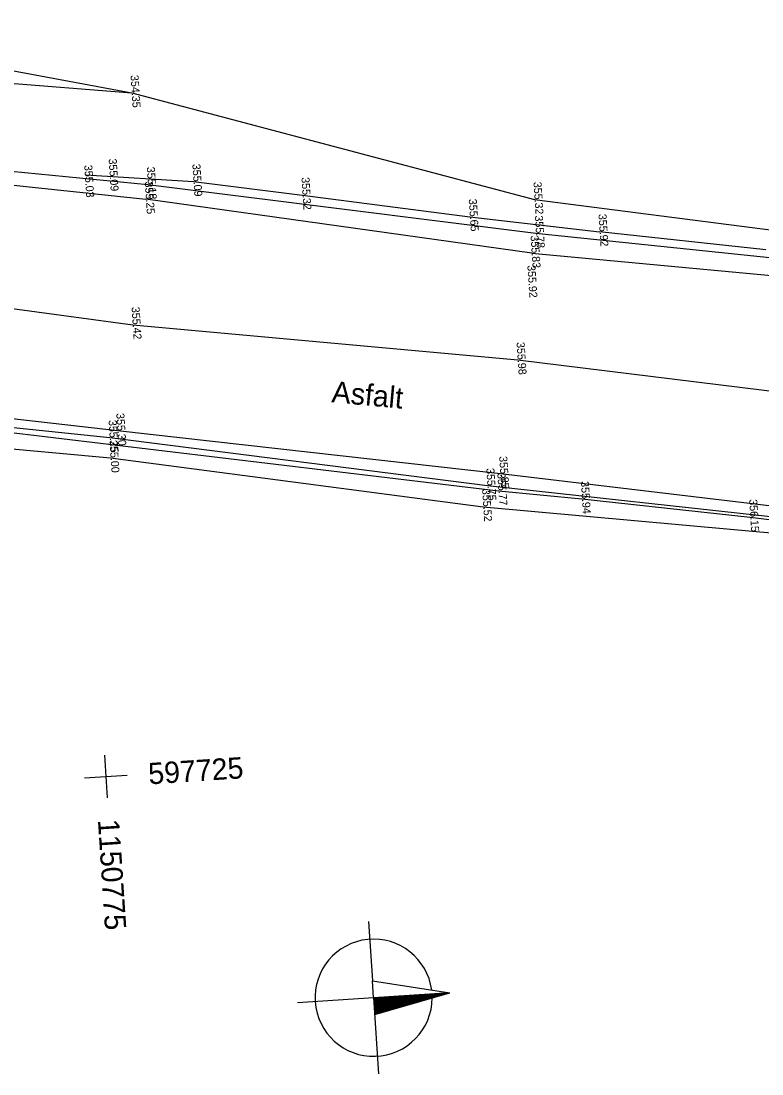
# Model space of a CAD drawing. Extents: x -600096 to -597522, y -1151695 to -1149849.
# Drawn here: x -599571.03 to -599553.67, y -1151449.97 to -1151425.31 of the extents above; entities that cross this region are included whole.
import ezdxf

# ---------------------------------------------------------------- set-up
doc = ezdxf.new("R2010")
doc.units = 0
for name, color, linetype in [('Hrana komunikace', 7, 'Continuous'), ('MPPV_Dno_prikopu', 7, 'Continuous'), ('MPPV_komunikace', 7, 'Continuous'), ('MPPV_svah', 7, 'Continuous'), ('MPPV_vodorovne_znaceni', 7, 'Continuous'), ('Popis', 7, 'Continuous'), ('rám', 7, 'Continuous'), ('Svodidla', 7, 'Continuous'), ('Tabulka', 7, 'Continuous'), ('Vrstva 12', 7, 'Continuous'), ('Vrstva 5', 7, 'Continuous')]:
    doc.layers.add(name, color=color, linetype=linetype)

msp = doc.modelspace()

# ---------------------------------------------------------------- linework, layer by layer
at = {"layer": 'Hrana komunikace'}
for p, q in [((-599577.687, -1151428.205), (-599568.056, -1151429.139)), ((-599568.056, -1151429.139), (-599558.962, -1151430.28)), ((-599558.962, -1151430.28), (-599551.698, -1151431.028)), ((-599568.951, -1151435.07), (-599578.396, -1151434.083)), ((-599560.099, -1151436.196), (-599568.951, -1151435.07)), ((-599552.65, -1151437.013), (-599560.099, -1151436.196))]:
    msp.add_line(p, q, dxfattribs=at)
at = {"layer": 'MPPV_Dno_prikopu'}
msp.add_line((-599577.724, -1151426.253), (-599568.437, -1151426.99), dxfattribs=at)
at = {"layer": 'MPPV_komunikace'}
for p, q in [((-599577.67, -1151428.464), (-599568.103, -1151429.483)), ((-599559.062, -1151430.747), (-599568.103, -1151429.483)), ((-599559.062, -1151430.747), (-599551.661, -1151431.436)), ((-599568.772, -1151434.908), (-599578.354, -1151433.8)), ((-599559.797, -1151435.916), (-599568.772, -1151434.908)), ((-599552.616, -1151436.77), (-599559.797, -1151435.916))]:
    msp.add_line(p, q, dxfattribs=at)
at = {"layer": 'MPPV_svah'}
for p, q in [((-599577.525, -1151425.308), (-599568.437, -1151426.99)), ((-599568.437, -1151426.99), (-599558.994, -1151429.49)), ((-599558.994, -1151429.49), (-599551.627, -1151430.432)), ((-599578.539, -1151434.654), (-599568.931, -1151435.54)), ((-599568.931, -1151435.54), (-599560.198, -1151436.684)), ((-599560.198, -1151436.684), (-599552.758, -1151437.36))]:
    msp.add_line(p, q, dxfattribs=at)
at = {"layer": 'MPPV_vodorovne_znaceni'}
for p, q in [((-599578.149, -1151431.111), (-599568.413, -1151432.42)), ((-599568.413, -1151432.42), (-599559.39, -1151433.244)), ((-599559.39, -1151433.244), (-599552.227, -1151434.129))]:
    msp.add_line(p, q, dxfattribs=at)
at = {"layer": 'rám'}
for p, q in [((-599562.767, -1151448.185), (-599562.767, -1151448.197)), ((-599562.762, -1151448.184), (-599562.764, -1151448.24)), ((-599562.757, -1151448.184), (-599562.761, -1151448.284)), ((-599562.752, -1151448.184), (-599562.758, -1151448.327)), ((-599562.747, -1151448.183), (-599562.755, -1151448.371)), ((-599562.742, -1151448.183), (-599562.753, -1151448.415)), ((-599562.737, -1151448.183), (-599562.75, -1151448.458)), ((-599562.732, -1151448.183), (-599562.747, -1151448.502)), ((-599562.727, -1151448.182), (-599562.744, -1151448.546)), ((-599562.721, -1151448.182), (-599562.74, -1151448.58)), ((-599562.716, -1151448.182), (-599562.735, -1151448.579)), ((-599562.711, -1151448.181), (-599562.73, -1151448.577)), ((-599562.706, -1151448.181), (-599562.725, -1151448.576)), ((-599562.701, -1151448.181), (-599562.72, -1151448.574)), ((-599562.696, -1151448.18), (-599562.715, -1151448.573)), ((-599562.691, -1151448.18), (-599562.71, -1151448.571)), ((-599562.686, -1151448.18), (-599562.705, -1151448.57)), ((-599562.681, -1151448.179), (-599562.7, -1151448.568)), ((-599562.676, -1151448.179), (-599562.695, -1151448.567)), ((-599562.671, -1151448.179), (-599562.69, -1151448.565)), ((-599562.666, -1151448.178), (-599562.685, -1151448.564)), ((-599562.661, -1151448.178), (-599562.679, -1151448.562)), ((-599562.656, -1151448.178), (-599562.674, -1151448.561)), ((-599562.651, -1151448.177), (-599562.669, -1151448.56)), ((-599562.646, -1151448.177), (-599562.664, -1151448.558)), ((-599562.641, -1151448.177), (-599562.659, -1151448.557)), ((-599562.636, -1151448.176), (-599562.654, -1151448.555)), ((-599562.631, -1151448.176), (-599562.649, -1151448.554)), ((-599562.626, -1151448.176), (-599562.644, -1151448.552)), ((-599562.621, -1151448.175), (-599562.639, -1151448.551)), ((-599562.616, -1151448.175), (-599562.634, -1151448.549)), ((-599562.611, -1151448.175), (-599562.629, -1151448.548)), ((-599562.606, -1151448.174), (-599562.624, -1151448.546)), ((-599562.601, -1151448.174), (-599562.619, -1151448.545)), ((-599562.596, -1151448.174), (-599562.613, -1151448.543)), ((-599562.591, -1151448.173), (-599562.608, -1151448.542)), ((-599562.586, -1151448.173), (-599562.603, -1151448.54)), ((-599562.581, -1151448.173), (-599562.598, -1151448.539)), ((-599562.576, -1151448.172), (-599562.593, -1151448.537)), ((-599562.571, -1151448.172), (-599562.588, -1151448.536)), ((-599562.566, -1151448.172), (-599562.583, -1151448.534)), ((-599562.561, -1151448.171), (-599562.578, -1151448.533)), ((-599562.556, -1151448.171), (-599562.573, -1151448.531)), ((-599562.551, -1151448.171), (-599562.568, -1151448.53)), ((-599562.546, -1151448.17), (-599562.563, -1151448.528)), ((-599562.541, -1151448.17), (-599562.558, -1151448.527)), ((-599562.536, -1151448.17), (-599562.553, -1151448.526)), ((-599562.531, -1151448.169), (-599562.547, -1151448.524)), ((-599562.526, -1151448.169), (-599562.542, -1151448.523)), ((-599562.521, -1151448.169), (-599562.537, -1151448.521)), ((-599562.516, -1151448.168), (-599562.532, -1151448.52)), ((-599562.511, -1151448.168), (-599562.527, -1151448.518)), ((-599562.506, -1151448.168), (-599562.522, -1151448.517)), ((-599562.501, -1151448.167), (-599562.517, -1151448.515)), ((-599562.496, -1151448.167), (-599562.512, -1151448.514)), ((-599562.491, -1151448.167), (-599562.507, -1151448.512)), ((-599562.486, -1151448.166), (-599562.502, -1151448.511)), ((-599562.48, -1151448.166), (-599562.497, -1151448.509)), ((-599562.475, -1151448.166), (-599562.492, -1151448.508)), ((-599562.47, -1151448.165), (-599562.487, -1151448.506)), ((-599562.465, -1151448.165), (-599562.481, -1151448.505)), ((-599562.46, -1151448.165), (-599562.476, -1151448.503)), ((-599562.455, -1151448.164), (-599562.471, -1151448.502)), ((-599562.45, -1151448.164), (-599562.466, -1151448.5)), ((-599562.445, -1151448.164), (-599562.461, -1151448.499)), ((-599562.44, -1151448.164), (-599562.456, -1151448.497)), ((-599562.435, -1151448.163), (-599562.451, -1151448.496)), ((-599562.43, -1151448.163), (-599562.446, -1151448.494)), ((-599562.425, -1151448.163), (-599562.441, -1151448.493)), ((-599562.42, -1151448.162), (-599562.436, -1151448.492)), ((-599562.415, -1151448.162), (-599562.431, -1151448.49)), ((-599562.41, -1151448.162), (-599562.426, -1151448.489)), ((-599562.405, -1151448.161), (-599562.421, -1151448.487)), ((-599562.4, -1151448.161), (-599562.416, -1151448.486)), ((-599562.395, -1151448.161), (-599562.41, -1151448.484)), ((-599562.39, -1151448.16), (-599562.405, -1151448.483)), ((-599562.385, -1151448.16), (-599562.4, -1151448.481)), ((-599562.38, -1151448.16), (-599562.395, -1151448.48)), ((-599562.375, -1151448.159), (-599562.39, -1151448.478)), ((-599562.37, -1151448.159), (-599562.385, -1151448.477)), ((-599562.365, -1151448.159), (-599562.38, -1151448.475)), ((-599562.36, -1151448.158), (-599562.375, -1151448.474)), ((-599562.355, -1151448.158), (-599562.37, -1151448.472)), ((-599562.35, -1151448.158), (-599562.365, -1151448.471)), ((-599562.345, -1151448.157), (-599562.36, -1151448.469)), ((-599562.34, -1151448.157), (-599562.355, -1151448.468)), ((-599562.335, -1151448.157), (-599562.35, -1151448.466)), ((-599562.33, -1151448.156), (-599562.344, -1151448.465)), ((-599562.325, -1151448.156), (-599562.339, -1151448.463)), ((-599562.32, -1151448.156), (-599562.334, -1151448.462)), ((-599562.315, -1151448.155), (-599562.329, -1151448.461)), ((-599562.31, -1151448.155), (-599562.324, -1151448.459)), ((-599562.305, -1151448.155), (-599562.319, -1151448.458)), ((-599562.3, -1151448.154), (-599562.314, -1151448.456)), ((-599562.295, -1151448.154), (-599562.309, -1151448.455)), ((-599562.29, -1151448.154), (-599562.304, -1151448.453)), ((-599562.285, -1151448.153), (-599562.299, -1151448.452)), ((-599562.28, -1151448.153), (-599562.294, -1151448.45)), ((-599562.275, -1151448.153), (-599562.289, -1151448.449)), ((-599562.27, -1151448.152), (-599562.284, -1151448.447)), ((-599562.265, -1151448.152), (-599562.278, -1151448.446)), ((-599562.26, -1151448.152), (-599562.273, -1151448.444)), ((-599562.255, -1151448.151), (-599562.268, -1151448.443)), ((-599562.25, -1151448.151), (-599562.263, -1151448.441)), ((-599562.244, -1151448.151), (-599562.258, -1151448.44)), ((-599562.239, -1151448.15), (-599562.253, -1151448.438)), ((-599562.234, -1151448.15), (-599562.248, -1151448.437)), ((-599562.229, -1151448.15), (-599562.243, -1151448.435)), ((-599562.224, -1151448.149), (-599562.238, -1151448.434)), ((-599562.219, -1151448.149), (-599562.233, -1151448.432)), ((-599562.214, -1151448.149), (-599562.228, -1151448.431)), ((-599562.209, -1151448.148), (-599562.223, -1151448.429)), ((-599562.204, -1151448.148), (-599562.218, -1151448.428)), ((-599562.199, -1151448.148), (-599562.212, -1151448.427)), ((-599562.194, -1151448.147), (-599562.207, -1151448.425)), ((-599562.189, -1151448.147), (-599562.202, -1151448.424)), ((-599562.184, -1151448.147), (-599562.197, -1151448.422)), ((-599562.179, -1151448.146), (-599562.192, -1151448.421)), ((-599562.174, -1151448.146), (-599562.187, -1151448.419)), ((-599562.169, -1151448.146), (-599562.182, -1151448.418)), ((-599562.164, -1151448.145), (-599562.177, -1151448.416)), ((-599562.159, -1151448.145), (-599562.172, -1151448.415)), ((-599562.154, -1151448.145), (-599562.167, -1151448.413)), ((-599562.149, -1151448.144), (-599562.162, -1151448.412)), ((-599562.144, -1151448.144), (-599562.157, -1151448.41)), ((-599562.139, -1151448.144), (-599562.152, -1151448.409)), ((-599562.134, -1151448.144), (-599562.147, -1151448.407)), ((-599562.129, -1151448.143), (-599562.141, -1151448.406)), ((-599562.124, -1151448.143), (-599562.136, -1151448.404)), ((-599562.119, -1151448.143), (-599562.131, -1151448.403)), ((-599562.114, -1151448.142), (-599562.126, -1151448.401)), ((-599562.109, -1151448.142), (-599562.121, -1151448.4)), ((-599562.104, -1151448.142), (-599562.116, -1151448.398)), ((-599562.099, -1151448.141), (-599562.111, -1151448.397)), ((-599562.094, -1151448.141), (-599562.106, -1151448.395)), ((-599562.089, -1151448.141), (-599562.101, -1151448.394)), ((-599562.084, -1151448.14), (-599562.096, -1151448.393)), ((-599562.079, -1151448.14), (-599562.091, -1151448.391)), ((-599562.074, -1151448.14), (-599562.086, -1151448.39)), ((-599562.069, -1151448.139), (-599562.081, -1151448.388)), ((-599562.064, -1151448.139), (-599562.075, -1151448.387)), ((-599562.059, -1151448.139), (-599562.07, -1151448.385)), ((-599562.054, -1151448.138), (-599562.065, -1151448.384)), ((-599562.049, -1151448.138), (-599562.06, -1151448.382)), ((-599562.044, -1151448.138), (-599562.055, -1151448.381)), ((-599562.039, -1151448.137), (-599562.05, -1151448.379)), ((-599562.034, -1151448.137), (-599562.045, -1151448.378)), ((-599562.029, -1151448.137), (-599562.04, -1151448.376)), ((-599562.024, -1151448.136), (-599562.035, -1151448.375)), ((-599562.019, -1151448.136), (-599562.03, -1151448.373)), ((-599562.014, -1151448.136), (-599562.025, -1151448.372)), ((-599562.008, -1151448.135), (-599562.02, -1151448.37)), ((-599562.003, -1151448.135), (-599562.015, -1151448.369)), ((-599561.998, -1151448.135), (-599562.009, -1151448.367)), ((-599561.993, -1151448.134), (-599562.004, -1151448.366)), ((-599561.988, -1151448.134), (-599561.999, -1151448.364)), ((-599561.983, -1151448.134), (-599561.994, -1151448.363)), ((-599561.978, -1151448.133), (-599561.989, -1151448.361)), ((-599561.973, -1151448.133), (-599561.984, -1151448.36)), ((-599561.968, -1151448.133), (-599561.979, -1151448.359)), ((-599561.963, -1151448.132), (-599561.974, -1151448.357)), ((-599561.958, -1151448.132), (-599561.969, -1151448.356)), ((-599561.953, -1151448.132), (-599561.964, -1151448.354)), ((-599561.948, -1151448.131), (-599561.959, -1151448.353)), ((-599561.943, -1151448.131), (-599561.954, -1151448.351)), ((-599561.938, -1151448.131), (-599561.949, -1151448.35)), ((-599561.933, -1151448.13), (-599561.943, -1151448.348)), ((-599561.928, -1151448.13), (-599561.938, -1151448.347)), ((-599561.923, -1151448.13), (-599561.933, -1151448.345)), ((-599561.918, -1151448.129), (-599561.928, -1151448.344)), ((-599561.913, -1151448.129), (-599561.923, -1151448.342)), ((-599561.908, -1151448.129), (-599561.918, -1151448.341)), ((-599561.903, -1151448.128), (-599561.913, -1151448.339)), ((-599561.898, -1151448.128), (-599561.908, -1151448.338)), ((-599561.893, -1151448.128), (-599561.903, -1151448.336)), ((-599561.888, -1151448.127), (-599561.898, -1151448.335)), ((-599561.883, -1151448.127), (-599561.893, -1151448.333)), ((-599561.878, -1151448.127), (-599561.888, -1151448.332)), ((-599561.873, -1151448.126), (-599561.883, -1151448.33)), ((-599561.868, -1151448.126), (-599561.878, -1151448.329)), ((-599561.863, -1151448.126), (-599561.872, -1151448.327)), ((-599561.858, -1151448.125), (-599561.867, -1151448.326)), ((-599561.853, -1151448.125), (-599561.862, -1151448.325)), ((-599561.848, -1151448.125), (-599561.857, -1151448.323)), ((-599561.843, -1151448.125), (-599561.852, -1151448.322)), ((-599561.838, -1151448.124), (-599561.847, -1151448.32)), ((-599561.833, -1151448.124), (-599561.842, -1151448.319)), ((-599561.828, -1151448.124), (-599561.837, -1151448.317)), ((-599561.823, -1151448.123), (-599561.832, -1151448.316)), ((-599561.818, -1151448.123), (-599561.827, -1151448.314)), ((-599561.813, -1151448.123), (-599561.822, -1151448.313)), ((-599561.808, -1151448.122), (-599561.817, -1151448.311)), ((-599561.803, -1151448.122), (-599561.812, -1151448.31)), ((-599561.798, -1151448.122), (-599561.806, -1151448.308)), ((-599561.793, -1151448.121), (-599561.801, -1151448.307)), ((-599561.788, -1151448.121), (-599561.796, -1151448.305)), ((-599561.783, -1151448.121), (-599561.791, -1151448.304)), ((-599561.778, -1151448.12), (-599561.786, -1151448.302)), ((-599561.773, -1151448.12), (-599561.781, -1151448.301)), ((-599561.767, -1151448.12), (-599561.776, -1151448.299)), ((-599561.762, -1151448.119), (-599561.771, -1151448.298)), ((-599561.757, -1151448.119), (-599561.766, -1151448.296)), ((-599561.752, -1151448.119), (-599561.761, -1151448.295)), ((-599561.747, -1151448.118), (-599561.756, -1151448.294)), ((-599561.742, -1151448.118), (-599561.751, -1151448.292)), ((-599561.737, -1151448.118), (-599561.746, -1151448.291)), ((-599561.732, -1151448.117), (-599561.74, -1151448.289)), ((-599561.727, -1151448.117), (-599561.735, -1151448.288)), ((-599561.722, -1151448.117), (-599561.73, -1151448.286)), ((-599561.717, -1151448.116), (-599561.725, -1151448.285)), ((-599561.712, -1151448.116), (-599561.72, -1151448.283)), ((-599561.707, -1151448.116), (-599561.715, -1151448.282)), ((-599561.702, -1151448.115), (-599561.71, -1151448.28)), ((-599561.697, -1151448.115), (-599561.705, -1151448.279)), ((-599561.692, -1151448.115), (-599561.7, -1151448.277)), ((-599561.687, -1151448.114), (-599561.695, -1151448.276)), ((-599561.682, -1151448.114), (-599561.69, -1151448.274)), ((-599561.677, -1151448.114), (-599561.685, -1151448.273)), ((-599561.672, -1151448.113), (-599561.68, -1151448.271)), ((-599561.667, -1151448.113), (-599561.674, -1151448.27)), ((-599561.662, -1151448.113), (-599561.669, -1151448.268)), ((-599561.657, -1151448.112), (-599561.664, -1151448.267)), ((-599561.652, -1151448.112), (-599561.659, -1151448.265)), ((-599561.647, -1151448.112), (-599561.654, -1151448.264)), ((-599561.642, -1151448.111), (-599561.649, -1151448.262)), ((-599561.637, -1151448.111), (-599561.644, -1151448.261)), ((-599561.632, -1151448.111), (-599561.639, -1151448.26)), ((-599561.627, -1151448.11), (-599561.634, -1151448.258)), ((-599561.622, -1151448.11), (-599561.629, -1151448.257)), ((-599561.617, -1151448.11), (-599561.624, -1151448.255)), ((-599561.612, -1151448.109), (-599561.619, -1151448.254)), ((-599561.607, -1151448.109), (-599561.614, -1151448.252)), ((-599561.602, -1151448.109), (-599561.609, -1151448.251)), ((-599561.597, -1151448.108), (-599561.603, -1151448.249)), ((-599561.592, -1151448.108), (-599561.598, -1151448.248)), ((-599561.587, -1151448.108), (-599561.593, -1151448.246)), ((-599561.582, -1151448.107), (-599561.588, -1151448.245)), ((-599561.577, -1151448.107), (-599561.583, -1151448.243)), ((-599561.572, -1151448.107), (-599561.578, -1151448.242)), ((-599561.567, -1151448.106), (-599561.573, -1151448.24)), ((-599561.562, -1151448.106), (-599561.568, -1151448.239)), ((-599561.557, -1151448.106), (-599561.563, -1151448.237)), ((-599561.552, -1151448.105), (-599561.558, -1151448.236)), ((-599561.547, -1151448.105), (-599561.553, -1151448.234)), ((-599561.542, -1151448.105), (-599561.548, -1151448.233)), ((-599561.537, -1151448.105), (-599561.543, -1151448.231)), ((-599561.531, -1151448.104), (-599561.537, -1151448.23)), ((-599561.526, -1151448.104), (-599561.532, -1151448.228)), ((-599561.521, -1151448.104), (-599561.527, -1151448.227)), ((-599561.516, -1151448.103), (-599561.522, -1151448.226)), ((-599561.511, -1151448.103), (-599561.517, -1151448.224)), ((-599561.506, -1151448.103), (-599561.512, -1151448.223)), ((-599561.501, -1151448.102), (-599561.507, -1151448.221)), ((-599561.496, -1151448.102), (-599561.502, -1151448.22)), ((-599561.491, -1151448.102), (-599561.497, -1151448.218)), ((-599561.486, -1151448.101), (-599561.492, -1151448.217)), ((-599561.481, -1151448.101), (-599561.487, -1151448.215)), ((-599561.476, -1151448.101), (-599561.482, -1151448.214)), ((-599561.471, -1151448.1), (-599561.477, -1151448.212)), ((-599561.466, -1151448.1), (-599561.471, -1151448.211)), ((-599561.461, -1151448.1), (-599561.466, -1151448.209)), ((-599561.456, -1151448.099), (-599561.461, -1151448.208)), ((-599561.451, -1151448.099), (-599561.456, -1151448.206)), ((-599561.446, -1151448.099), (-599561.451, -1151448.205)), ((-599561.441, -1151448.098), (-599561.446, -1151448.203)), ((-599561.436, -1151448.098), (-599561.441, -1151448.202)), ((-599561.431, -1151448.098), (-599561.436, -1151448.2)), ((-599561.426, -1151448.097), (-599561.431, -1151448.199)), ((-599561.421, -1151448.097), (-599561.426, -1151448.197)), ((-599561.416, -1151448.097), (-599561.421, -1151448.196)), ((-599561.411, -1151448.096), (-599561.416, -1151448.194)), ((-599561.406, -1151448.096), (-599561.411, -1151448.193)), ((-599561.401, -1151448.096), (-599561.405, -1151448.192)), ((-599561.396, -1151448.095), (-599561.4, -1151448.19)), ((-599561.391, -1151448.095), (-599561.395, -1151448.189)), ((-599561.386, -1151448.095), (-599561.39, -1151448.187)), ((-599561.381, -1151448.094), (-599561.385, -1151448.186)), ((-599561.376, -1151448.094), (-599561.38, -1151448.184)), ((-599561.371, -1151448.094), (-599561.375, -1151448.183)), ((-599561.366, -1151448.093), (-599561.37, -1151448.181)), ((-599561.361, -1151448.093), (-599561.365, -1151448.18)), ((-599561.356, -1151448.093), (-599561.36, -1151448.178)), ((-599561.351, -1151448.092), (-599561.355, -1151448.177)), ((-599561.346, -1151448.092), (-599561.35, -1151448.175)), ((-599561.341, -1151448.092), (-599561.345, -1151448.174)), ((-599561.336, -1151448.091), (-599561.339, -1151448.172)), ((-599561.331, -1151448.091), (-599561.334, -1151448.171)), ((-599561.326, -1151448.091), (-599561.329, -1151448.169)), ((-599561.321, -1151448.09), (-599561.324, -1151448.168)), ((-599561.316, -1151448.09), (-599561.319, -1151448.166)), ((-599561.311, -1151448.09), (-599561.314, -1151448.165)), ((-599561.306, -1151448.089), (-599561.309, -1151448.163)), ((-599561.301, -1151448.089), (-599561.304, -1151448.162)), ((-599561.295, -1151448.089), (-599561.299, -1151448.161)), ((-599561.29, -1151448.088), (-599561.294, -1151448.159)), ((-599561.285, -1151448.088), (-599561.289, -1151448.158)), ((-599561.28, -1151448.088), (-599561.284, -1151448.156)), ((-599561.275, -1151448.087), (-599561.279, -1151448.155)), ((-599561.27, -1151448.087), (-599561.274, -1151448.153)), ((-599561.265, -1151448.087), (-599561.268, -1151448.152)), ((-599561.26, -1151448.086), (-599561.263, -1151448.15)), ((-599561.255, -1151448.086), (-599561.258, -1151448.149)), ((-599561.25, -1151448.086), (-599561.253, -1151448.147)), ((-599561.245, -1151448.085), (-599561.248, -1151448.146)), ((-599561.24, -1151448.085), (-599561.243, -1151448.144)), ((-599561.235, -1151448.085), (-599561.238, -1151448.143)), ((-599561.23, -1151448.085), (-599561.233, -1151448.141)), ((-599561.225, -1151448.084), (-599561.228, -1151448.14)), ((-599561.22, -1151448.084), (-599561.223, -1151448.138)), ((-599561.215, -1151448.084), (-599561.218, -1151448.137)), ((-599561.21, -1151448.083), (-599561.213, -1151448.135)), ((-599561.205, -1151448.083), (-599561.208, -1151448.134)), ((-599561.2, -1151448.083), (-599561.202, -1151448.132)), ((-599561.195, -1151448.082), (-599561.197, -1151448.131)), ((-599561.19, -1151448.082), (-599561.192, -1151448.129)), ((-599561.185, -1151448.082), (-599561.187, -1151448.128)), ((-599561.18, -1151448.081), (-599561.182, -1151448.127)), ((-599561.175, -1151448.081), (-599561.177, -1151448.125)), ((-599561.17, -1151448.081), (-599561.172, -1151448.124)), ((-599561.165, -1151448.08), (-599561.167, -1151448.122)), ((-599561.16, -1151448.08), (-599561.162, -1151448.121)), ((-599561.155, -1151448.08), (-599561.157, -1151448.119)), ((-599561.15, -1151448.079), (-599561.152, -1151448.118)), ((-599561.145, -1151448.079), (-599561.147, -1151448.116)), ((-599561.14, -1151448.079), (-599561.142, -1151448.115)), ((-599561.135, -1151448.078), (-599561.136, -1151448.113)), ((-599561.13, -1151448.078), (-599561.131, -1151448.112)), ((-599561.125, -1151448.078), (-599561.126, -1151448.11)), ((-599561.12, -1151448.077), (-599561.121, -1151448.109)), ((-599561.115, -1151448.077), (-599561.116, -1151448.107)), ((-599561.11, -1151448.077), (-599561.111, -1151448.106)), ((-599561.105, -1151448.076), (-599561.106, -1151448.104)), ((-599561.1, -1151448.076), (-599561.101, -1151448.103)), ((-599561.095, -1151448.076), (-599561.096, -1151448.101)), ((-599561.09, -1151448.075), (-599561.091, -1151448.1)), ((-599561.085, -1151448.075), (-599561.086, -1151448.098)), ((-599561.08, -1151448.075), (-599561.081, -1151448.097)), ((-599561.075, -1151448.074), (-599561.076, -1151448.095)), ((-599561.07, -1151448.074), (-599561.07, -1151448.094)), ((-599561.065, -1151448.074), (-599561.065, -1151448.093)), ((-599561.06, -1151448.073), (-599561.06, -1151448.091)), ((-599561.054, -1151448.073), (-599561.055, -1151448.09)), ((-599561.049, -1151448.073), (-599561.05, -1151448.088)), ((-599561.044, -1151448.072), (-599561.045, -1151448.087)), ((-599561.039, -1151448.072), (-599561.04, -1151448.085)), ((-599561.034, -1151448.072), (-599561.035, -1151448.084)), ((-599561.029, -1151448.071), (-599561.03, -1151448.082)), ((-599561.024, -1151448.071), (-599561.025, -1151448.081)), ((-599561.019, -1151448.071), (-599561.02, -1151448.079)), ((-599561.014, -1151448.07), (-599561.015, -1151448.078)), ((-599561.009, -1151448.07), (-599561.01, -1151448.076)), ((-599561.004, -1151448.07), (-599561.005, -1151448.075)), ((-599560.999, -1151448.069), (-599560.999, -1151448.073)), ((-599560.994, -1151448.069), (-599560.994, -1151448.072)), ((-599560.989, -1151448.069), (-599560.989, -1151448.07)), ((-599560.984, -1151448.068), (-599560.984, -1151448.069))]:
    msp.add_line(p, q, dxfattribs=at)
at = {"layer": 'Svodidla'}
for p, q in [((-599569.51, -1151428.912), (-599566.988, -1151429.07)), ((-599566.988, -1151429.07), (-599564.432, -1151429.384)), ((-599564.432, -1151429.384), (-599560.511, -1151429.89)), ((-599560.511, -1151429.89), (-599557.471, -1151430.242)), ((-599553.575, -1151430.67), (-599557.471, -1151430.242)), ((-599571.76, -1151434.883), (-599559.841, -1151436.31)), ((-599559.841, -1151436.31), (-599557.885, -1151436.503)), ((-599557.885, -1151436.503), (-599553.939, -1151436.926)), ((-599553.939, -1151436.926), (-599550.018, -1151437.422))]:
    msp.add_line(p, q, dxfattribs=at)
at = {"layer": 'Tabulka'}
for p, q in [((-599562.886, -1151446.4), (-599562.794, -1151447.789)), ((-599562.768, -1151448.185), (-599562.794, -1151447.789)), ((-599562.794, -1151447.789), (-599560.982, -1151448.068)), ((-599562.768, -1151448.185), (-599564.552, -1151448.301)), ((-599560.982, -1151448.068), (-599562.768, -1151448.185)), ((-599560.982, -1151448.068), (-599562.768, -1151448.185)), ((-599562.768, -1151448.185), (-599562.65, -1151449.97)), ((-599562.768, -1151448.185), (-599562.741, -1151448.581)), ((-599562.741, -1151448.581), (-599560.982, -1151448.068))]:
    msp.add_line(p, q, dxfattribs=at)
msp.add_arc((-599562.767, -1151448.185), 1.373, 7.6478, 359.8838, dxfattribs=at)
at = {"layer": 'Vrstva 5'}
for points in [[(-599569.077, -1151442.504), (-599569.045, -1151443.003), (-599569.012, -1151443.502)], [(-599569.544, -1151443.036), (-599569.045, -1151443.003), (-599568.546, -1151442.971)]]:
    msp.add_lwpolyline(points, dxfattribs=at)

# ---------------------------------------------------------------- texts
at = {"layer": 'Popis'}
msp.add_text('Asfalt', height=0.5, rotation=354.7672, dxfattribs=at).set_placement((-599563.763, -1151434.235))
at = {"layer": 'Vrstva 12'}
for s, p in [('354.35 ', (-599568.464, -1151426.577)), ('355.03 ', (-599569.549, -1151428.683)), ('355.09 ', (-599568.977, -1151428.535)), ('355.18 ', (-599568.083, -1151428.727)), ('355.09 ', (-599567.015, -1151428.658)), ('355.32 ', (-599564.459, -1151428.972)), ('355.25 ', (-599568.13, -1151429.071)), ('355.32 ', (-599559.021, -1151429.078)), ('355.65 ', (-599560.538, -1151429.477)), ('355.78 ', (-599558.989, -1151429.867)), ('355.92 ', (-599557.498, -1151429.83)), ('355.83 ', (-599559.089, -1151430.335)), ('355.92 ', (-599559.164, -1151431.031)), ('355.42 ', (-599568.44, -1151432.007)), ('355.98 ', (-599559.417, -1151432.832)), ('355.30 ', (-599568.798, -1151434.496)), ('355.25 ', (-599568.978, -1151434.658)), ('355.00 ', (-599568.958, -1151435.128)), ('355.85 ', (-599559.824, -1151435.504)), ('355.75 ', (-599560.126, -1151435.784)), ('355.77 ', (-599559.868, -1151435.897)), ('355.94 ', (-599557.911, -1151436.09)), ('355.52 ', (-599560.225, -1151436.271)), ('356.15 ', (-599553.966, -1151436.514))]:
    msp.add_text(s, height=0.1875, rotation=273.7347, dxfattribs=at).set_placement(p)
at = {"layer": 'Vrstva 5'}
for s, rotation, p in [('597725', 3.7347, (-599568.031, -1151443.188)), ('1150775', 273.7347, (-599569.229, -1151444.018))]:
    msp.add_text(s, height=0.5, rotation=rotation, dxfattribs=at).set_placement(p)

doc.saveas('drawing.dxf')
